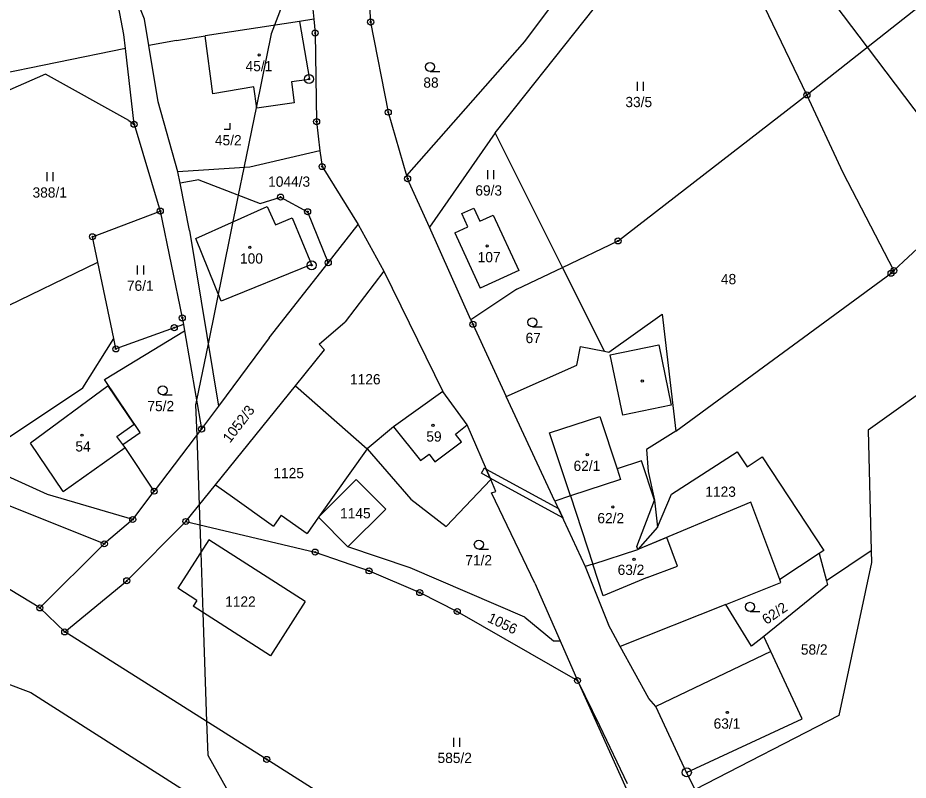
# Model space of a CAD drawing. Extents: x -547623 to -538651, y -1096714 to -1086522.
# Drawn here: x -539985 to -539837.5, y -1092582.7 to -1092456.3 of the extents above; entities that cross this region are included whole.
import ezdxf

# ---------------------------------------------------------------- set-up
doc = ezdxf.new("R2010")
doc.units = 0
for name, color, linetype in [('Vrstva 1', 7, 'Continuous'), ('Vrstva 25', 7, 'Continuous'), ('Vrstva 30', 7, 'Continuous'), ('Vrstva 33', 7, 'Continuous'), ('Vrstva 52', 7, 'Continuous'), ('Vrstva 83', 7, 'Continuous'), ('Vrstva 86', 7, 'Continuous'), ('Vrstva 90', 7, 'Continuous'), ('Vrstva 92', 7, 'Continuous')]:
    doc.layers.add(name, color=color, linetype=linetype)

msp = doc.modelspace()

# ---------------------------------------------------------------- linework, layer by layer
at = {"layer": 'Vrstva 1'}
for points in [[(-539854.24, -1092469.12), (-539880.19, -1092415.07)], [(-539927.51, -1092441.29), (-539926.51, -1092457.05)], [(-539854.24, -1092469.12), (-539819.88, -1092441.94)], [(-539889.99, -1092445.46), (-539901.05, -1092460.25)], [(-539967.38, -1092459.11), (-539969.34, -1092448.92)], [(-539963.99, -1092456.56), (-539966.38, -1092450.37)], [(-539936.59, -1092449.87), (-539935.93, -1092456.59)], [(-539905.87, -1092475.4), (-539886.21, -1092450.61)], [(-539963.24, -1092460.92), (-539963.99, -1092456.56)], [(-539938.3, -1092456.95), (-539953.92, -1092459.34)], [(-539935.93, -1092456.59), (-539938.3, -1092456.95)], [(-539938.3, -1092456.95), (-539936.64, -1092466.58)], [(-539935.93, -1092456.59), (-539935.71, -1092458.88)], [(-539926.51, -1092457.05), (-539923.6, -1092471.99)], [(-539967.12, -1092461.42), (-539967.38, -1092459.11)], [(-539958.7, -1092460.12), (-539953.92, -1092459.34)], [(-539952.63, -1092468.96), (-539953.92, -1092459.34)], [(-539935.71, -1092458.88), (-539935.47, -1092473.55)], [(-539958.7, -1092460.12), (-539963.24, -1092460.92)], [(-539961.69, -1092470.26), (-539963.24, -1092460.92)], [(-539901.05, -1092460.25), (-539920.55, -1092482.48)], [(-539967.12, -1092461.42), (-539989.83, -1092466.07)], [(-539965.7, -1092473.99), (-539967.12, -1092461.42)], [(-539980.4, -1092465.66), (-539988.59, -1092469.3)], [(-539966.56, -1092473.37), (-539980.4, -1092465.66)], [(-539936.64, -1092466.58), (-539939.65, -1092466.96)], [(-539939.65, -1092466.96), (-539939.18, -1092470.46)], [(-539945.89, -1092467.79), (-539952.63, -1092468.96)], [(-539945.39, -1092471.34), (-539945.89, -1092467.79)], [(-539885.53, -1092493.32), (-539854.24, -1092469.12)], [(-539848.22, -1092482.06), (-539854.24, -1092469.12)], [(-539958.44, -1092481.89), (-539961.69, -1092470.26)], [(-539939.18, -1092470.46), (-539945.39, -1092471.34)], [(-539923.6, -1092471.99), (-539920.55, -1092482.48)], [(-539966.56, -1092473.37), (-539965.7, -1092473.99)], [(-539965.7, -1092473.99), (-539961.36, -1092488.37)], [(-539935.47, -1092473.55), (-539934.94, -1092478.38)], [(-539905.87, -1092475.4), (-539916.79, -1092491.03)], [(-539894.73, -1092497.7), (-539905.87, -1092475.4)], [(-539934.94, -1092478.38), (-539946.54, -1092481.12)], [(-539934.94, -1092478.38), (-539934.55, -1092481)], [(-539946.54, -1092481.12), (-539958.44, -1092481.89)], [(-539958.08, -1092483.74), (-539958.44, -1092481.89)], [(-539934.55, -1092481), (-539928.56, -1092490.6)], [(-539954.99, -1092483.22), (-539958.08, -1092483.74)], [(-539954.99, -1092483.22), (-539944.84, -1092487.14)], [(-539920.55, -1092482.48), (-539920.39, -1092483.01)], [(-539916.79, -1092491.03), (-539920.39, -1092483.01)], [(-539839.84, -1092498.24), (-539848.22, -1092482.06)], [(-539956.54, -1092491.6), (-539958.08, -1092483.74)], [(-539944.84, -1092487.14), (-539941.44, -1092486.05)], [(-539941.44, -1092486.05), (-539936.95, -1092488.48)], [(-539911.4, -1092488.78), (-539909.4, -1092487.87)], [(-539909.4, -1092487.87), (-539908.41, -1092490.05)], [(-539972.59, -1092492.63), (-539961.36, -1092488.37)], [(-539961.36, -1092488.37), (-539957.71, -1092506.07)], [(-539936.95, -1092488.48), (-539933.54, -1092496.92)], [(-539910.41, -1092490.96), (-539911.4, -1092488.78)], [(-539908.41, -1092490.05), (-539906.22, -1092489.05)], [(-539906.22, -1092489.05), (-539901.94, -1092498.2)], [(-539933.54, -1092496.92), (-539928.56, -1092490.6)], [(-539928.56, -1092490.6), (-539924.33, -1092498.35)], [(-539956.54, -1092491.6), (-539951.73, -1092520.7)], [(-539909.9, -1092506.41), (-539916.79, -1092491.03)], [(-539912.59, -1092491.96), (-539910.41, -1092490.96)], [(-539912.59, -1092491.96), (-539908.39, -1092501.15)], [(-539971.72, -1092496.81), (-539972.59, -1092492.63)], [(-539894.73, -1092497.7), (-539885.53, -1092493.32)], [(-539835.1, -1092493.79), (-539839.84, -1092498.24)], [(-539988.4, -1092504.88), (-539971.72, -1092496.81)], [(-539969.08, -1092509.5), (-539971.72, -1092496.81)], [(-539943.33, -1092509.36), (-539933.54, -1092496.92)], [(-539901.94, -1092498.2), (-539908.39, -1092501.15)], [(-539902.28, -1092501.29), (-539894.73, -1092497.7)], [(-539887.8, -1092511.58), (-539894.73, -1092497.7)], [(-539839.84, -1092498.24), (-539840.31, -1092498.67)], [(-539924.33, -1092498.35), (-539930.72, -1092506.72)], [(-539924.33, -1092498.35), (-539914.58, -1092518.25)], [(-539875.95, -1092524.82), (-539840.31, -1092498.67)], [(-539902.28, -1092501.29), (-539909.9, -1092506.41)], [(-539887.07, -1092511.73), (-539878.25, -1092505.43)], [(-539878.25, -1092505.43), (-539875.95, -1092524.82)], [(-539957.71, -1092506.07), (-539957.53, -1092507.14)], [(-539935.02, -1092510.4), (-539930.72, -1092506.72)], [(-539909.9, -1092506.41), (-539909.57, -1092507.13)], [(-539970.58, -1092516.26), (-539957.34, -1092508.21)], [(-539959.05, -1092507.69), (-539968.72, -1092511.21)], [(-539957.53, -1092507.14), (-539959.05, -1092507.69)], [(-539957.53, -1092507.14), (-539957.34, -1092508.21)], [(-539957.34, -1092508.21), (-539954.52, -1092524.48)], [(-539909.57, -1092507.13), (-539904.06, -1092519.12)], [(-539974.2, -1092517.68), (-539969.08, -1092509.5)], [(-539968.72, -1092511.21), (-539969.08, -1092509.5)], [(-539943.33, -1092509.36), (-539951.73, -1092520.7)], [(-539938.96, -1092517.34), (-539934.14, -1092511.37)], [(-539934.14, -1092511.37), (-539935.02, -1092510.4)], [(-539892.37, -1092513.88), (-539891.75, -1092510.79)], [(-539891.75, -1092510.79), (-539887.8, -1092511.58)], [(-539887.8, -1092511.58), (-539887.07, -1092511.73)], [(-539904.06, -1092519.12), (-539892.37, -1092513.88)], [(-539831.12, -1092515.38), (-539844.08, -1092524.7)], [(-539964.68, -1092525.04), (-539970.58, -1092516.26)], [(-539952.21, -1092533.73), (-539938.96, -1092517.34)], [(-539938.96, -1092517.34), (-539927.08, -1092527.79)], [(-539992.38, -1092529.77), (-539974.2, -1092517.68)], [(-539914.58, -1092518.25), (-539922.72, -1092524.13)], [(-539910.51, -1092523.78), (-539914.58, -1092518.25)], [(-539895.99, -1092536.42), (-539904.06, -1092519.12)], [(-539951.73, -1092520.7), (-539954.52, -1092524.48)], [(-539970.63, -1092543.51), (-540021.91, -1092522.99)], [(-539954.52, -1092524.48), (-539962.37, -1092534.79)], [(-539922.72, -1092524.13), (-539927.08, -1092527.79)], [(-539906.6, -1092532.86), (-539910.51, -1092523.78)], [(-539844.08, -1092524.7), (-539843.61, -1092544.68)], [(-539967.54, -1092527.06), (-539964.68, -1092525.04)], [(-539875.95, -1092524.82), (-539880.81, -1092527.9)], [(-539967.18, -1092527.54), (-539967.54, -1092527.06)], [(-539962.37, -1092534.79), (-539967.18, -1092527.54)], [(-539927.08, -1092527.79), (-539935.14, -1092539.1)], [(-539927.08, -1092527.79), (-539919.83, -1092536.1)], [(-539880.81, -1092527.9), (-539880.55, -1092531.53)], [(-539876.69, -1092535.28), (-539865.82, -1092528.26)], [(-539865.82, -1092528.26), (-539864.17, -1092530.77)], [(-539864.17, -1092530.77), (-539861.65, -1092529.12)], [(-539861.65, -1092529.12), (-539851.46, -1092544.63)], [(-539980.04, -1092535.32), (-539992.38, -1092529.77)], [(-539881.62, -1092529.74), (-539885.7, -1092531.09)], [(-539879.47, -1092536.25), (-539881.62, -1092529.74)], [(-539885.7, -1092531.09), (-539885.12, -1092532.84)], [(-539880.55, -1092531.53), (-539879.47, -1092536.25)], [(-539928.89, -1092532.86), (-539935.14, -1092539.1)], [(-539924.02, -1092537.74), (-539928.89, -1092532.86)], [(-539914.01, -1092540.61), (-539906.6, -1092532.86)], [(-539905.75, -1092534.83), (-539906.6, -1092532.86)], [(-539885.12, -1092532.84), (-539893.43, -1092535.58)], [(-539965.93, -1092539.48), (-539962.37, -1092534.79)], [(-539957.12, -1092539.8), (-539952.21, -1092533.73)], [(-539952.21, -1092533.73), (-539949.81, -1092535.44)], [(-539906.5, -1092535.08), (-539905.75, -1092534.83)], [(-539899.29, -1092550.04), (-539906.5, -1092535.08)], [(-539965.93, -1092539.48), (-539980.04, -1092535.32)], [(-539949.81, -1092535.44), (-539942.61, -1092540.57)], [(-539919.83, -1092536.1), (-539914.01, -1092540.61)], [(-539893.43, -1092535.58), (-539895.99, -1092536.42)], [(-539895.99, -1092536.42), (-539890.96, -1092547.25)], [(-539879.47, -1092536.25), (-539879, -1092540.75)], [(-539879, -1092540.75), (-539876.69, -1092535.28)], [(-539981.31, -1092554.13), (-540009.05, -1092537.31)], [(-539930.27, -1092543.98), (-539924.02, -1092537.74)], [(-539863.53, -1092536.62), (-539882.25, -1092544.43)], [(-539858.74, -1092549.42), (-539863.53, -1092536.62)], [(-539965.93, -1092539.48), (-539970.63, -1092543.51)], [(-539941.31, -1092538.74), (-539942.61, -1092540.57)], [(-539941.31, -1092538.74), (-539937.05, -1092541.78)], [(-539935.14, -1092539.1), (-539937.05, -1092541.78)], [(-539930.27, -1092543.98), (-539935.14, -1092539.1)], [(-539966.91, -1092549.63), (-539957.12, -1092539.8)], [(-539957.12, -1092539.8), (-539935.71, -1092544.88)], [(-539879, -1092540.75), (-539882.25, -1092544.43)], [(-539970.63, -1092543.51), (-539981.31, -1092554.13)], [(-539953.32, -1092542.86), (-539958.45, -1092550.88)], [(-539937.35, -1092553.08), (-539953.32, -1092542.86)], [(-539935.71, -1092544.88), (-539926.78, -1092547.99)], [(-539919.98, -1092547.47), (-539930.27, -1092543.98)], [(-539889.7, -1092546.89), (-539882.25, -1092544.43)], [(-539852.21, -1092545.13), (-539858.74, -1092549.42)], [(-539851.46, -1092544.63), (-539852.21, -1092545.13)], [(-539852.21, -1092545.13), (-539851.02, -1092549.62)], [(-539843.61, -1092544.68), (-539851.02, -1092549.62)], [(-539843.61, -1092544.68), (-539843.55, -1092546.58)], [(-539889.7, -1092546.89), (-539890.96, -1092547.25)], [(-539843.55, -1092546.58), (-539848.95, -1092571.97)], [(-539926.78, -1092547.99), (-539918.39, -1092551.59)], [(-539900.95, -1092555.67), (-539919.98, -1092547.47)], [(-539890.96, -1092547.25), (-539887.13, -1092556.95)], [(-539977.19, -1092558.1), (-539966.91, -1092549.63)], [(-539858.56, -1092549.91), (-539858.74, -1092549.42)], [(-539851.02, -1092549.62), (-539850.83, -1092550.33)], [(-539955.3, -1092552.9), (-539958.45, -1092550.88)], [(-539899.29, -1092550.04), (-539895.12, -1092559.59)], [(-539867.66, -1092553.54), (-539858.56, -1092549.91)], [(-539850.83, -1092550.33), (-539861.4, -1092558.84)], [(-539918.39, -1092551.59), (-539912.17, -1092554.72)], [(-539981.31, -1092554.13), (-539977.19, -1092558.1)], [(-539955.3, -1092552.9), (-539955.9, -1092553.85)], [(-539943.08, -1092562.05), (-539955.9, -1092553.85)], [(-539937.35, -1092553.08), (-539943.08, -1092562.05)], [(-539867.66, -1092553.54), (-539885.17, -1092560.52)], [(-539863.44, -1092560.48), (-539867.66, -1092553.54)], [(-539912.17, -1092554.72), (-539892.25, -1092566.16)], [(-539900.95, -1092555.67), (-539896.24, -1092559.58)], [(-539885.17, -1092560.52), (-539887.13, -1092556.95)], [(-539943.72, -1092579.23), (-539977.19, -1092558.1)], [(-539896.24, -1092559.58), (-539895.12, -1092559.59)], [(-539895.12, -1092559.59), (-539892.25, -1092566.16)], [(-539861.4, -1092558.84), (-539863.44, -1092560.48)], [(-539860.22, -1092561.37), (-539861.4, -1092558.84)], [(-539880.44, -1092569.13), (-539885.17, -1092560.52)], [(-539855.04, -1092572.53), (-539860.22, -1092561.37)], [(-539987.04, -1092566.54), (-539982.78, -1092568.14)], [(-539892.25, -1092566.16), (-539876.34, -1092601.43)], [(-539892.25, -1092566.16), (-539888.59, -1092573.61)], [(-539982.78, -1092568.14), (-539937.51, -1092597.02)], [(-539879.27, -1092570.44), (-539880.44, -1092569.13)], [(-539874.17, -1092581.42), (-539879.27, -1092570.44)], [(-539848.95, -1092571.97), (-539872.78, -1092584.22)], [(-539874.17, -1092581.42), (-539855.04, -1092572.53)], [(-539888.59, -1092573.61), (-539884.01, -1092583.21)], [(-539930.72, -1092587.47), (-539943.72, -1092579.23)], [(-539872.78, -1092584.22), (-539874.17, -1092581.42)]]:
    msp.add_lwpolyline(points, dxfattribs=at)
at = {"layer": 'Vrstva 25'}
for p, q in [((-539916.68, -1092465.23), (-539915.08, -1092465.23)), ((-539882.3, -1092468.45), (-539882.3, -1092466.95)), ((-539881.3, -1092468.45), (-539881.3, -1092466.95)), ((-539980.11, -1092483.44), (-539980.11, -1092481.94)), ((-539979.11, -1092483.44), (-539979.11, -1092481.94)), ((-539907.11, -1092483.1), (-539907.11, -1092481.6)), ((-539906.11, -1092483.1), (-539906.11, -1092481.6)), ((-539965.11, -1092498.88), (-539965.11, -1092497.38)), ((-539964.11, -1092498.88), (-539964.11, -1092497.38)), ((-539899.71, -1092507.55), (-539898.11, -1092507.55)), ((-539960.98, -1092518.83), (-539959.38, -1092518.83)), ((-539908.59, -1092544.38), (-539906.99, -1092544.38)), ((-539863.66, -1092554.7), (-539862.06, -1092554.7)), ((-539912.75, -1092577.13), (-539912.75, -1092575.63)), ((-539911.75, -1092577.13), (-539911.75, -1092575.63))]:
    msp.add_line(p, q, dxfattribs=at)
msp.add_lwpolyline([(-539950.8, -1092474.78), (-539949.8, -1092474.78), (-539949.8, -1092473.78)], dxfattribs=at)
for centre, radius in [((-539944.99, -1092462.5), 0.175), ((-539916.68, -1092464.48), 0.75), ((-539946.52, -1092494.37), 0.175), ((-539907.22, -1092494.15), 0.175), ((-539899.71, -1092506.8), 0.75), ((-539960.98, -1092518.08), 0.75), ((-539881.51, -1092516.53), 0.175), ((-539916.19, -1092523.87), 0.175), ((-539974.32, -1092525.51), 0.175), ((-539890.62, -1092528.73), 0.175), ((-539886.4, -1092537.4), 0.175), ((-539908.59, -1092543.63), 0.75), ((-539882.88, -1092546.07), 0.175), ((-539863.66, -1092553.95), 0.75), ((-539867.42, -1092571.44), 0.175)]:
    msp.add_circle(centre, radius, dxfattribs=at)
at = {"layer": 'Vrstva 30'}
for points in [[(-539908.15, -1092531.82), (-539907.67, -1092530.94)], [(-539906.71, -1092532.61), (-539908.15, -1092531.82)], [(-539907.67, -1092530.94), (-539907.35, -1092531.11)], [(-539907.35, -1092531.11), (-539906.71, -1092532.61)], [(-539907.35, -1092531.11), (-539895.41, -1092537.67)], [(-539906.71, -1092532.61), (-539907.35, -1092531.11)], [(-539894.7, -1092539.19), (-539906.71, -1092532.61)], [(-539895.41, -1092537.67), (-539894.7, -1092539.19)]]:
    msp.add_lwpolyline(points, dxfattribs=at)
at = {"layer": 'Vrstva 33'}
for points in [[(-539955.48, -1092492.93), (-539943.63, -1092487.61)], [(-539943.63, -1092487.61), (-539942.26, -1092490.67)], [(-539942.26, -1092490.67), (-539939.51, -1092489.47)], [(-539939.51, -1092489.47), (-539936.3, -1092497.25)], [(-539951.27, -1092503.32), (-539955.48, -1092492.93)], [(-539936.3, -1092497.25), (-539951.27, -1092503.32)], [(-539886.81, -1092512.19), (-539878.78, -1092510.53)], [(-539878.78, -1092510.53), (-539876.72, -1092520.52)], [(-539884.75, -1092522.18), (-539886.81, -1092512.19)], [(-539969.99, -1092517.31), (-539982.88, -1092526.84)], [(-539965.69, -1092523.7), (-539969.99, -1092517.31)], [(-539876.72, -1092520.52), (-539884.75, -1092522.18)], [(-539896.87, -1092525.14), (-539888.56, -1092522.4)], [(-539888.56, -1092522.4), (-539885.7, -1092531.09)], [(-539968.55, -1092525.72), (-539965.69, -1092523.7)], [(-539922.72, -1092524.13), (-539918.26, -1092529.72)], [(-539912.43, -1092525.34), (-539910.51, -1092523.78)], [(-539967.54, -1092527.06), (-539968.55, -1092525.72)], [(-539911.47, -1092526.62), (-539912.43, -1092525.34)], [(-539893.43, -1092535.58), (-539896.87, -1092525.14)], [(-539977.44, -1092534.86), (-539982.88, -1092526.84)], [(-539977.44, -1092534.86), (-539967.18, -1092527.54)], [(-539915.86, -1092529.92), (-539911.47, -1092526.62)], [(-539918.26, -1092529.72), (-539916.82, -1092528.64)], [(-539916.82, -1092528.64), (-539915.86, -1092529.92)], [(-539893.43, -1092535.58), (-539889.7, -1092546.89)], [(-539882.4, -1092543.95), (-539879.47, -1092536.25)], [(-539877.46, -1092542.46), (-539882.25, -1092544.43)], [(-539875.7, -1092547.19), (-539877.46, -1092542.46)], [(-539882.25, -1092544.43), (-539882.4, -1092543.95)], [(-539888, -1092552.1), (-539889.7, -1092546.89)], [(-539880.71, -1092549.09), (-539875.7, -1092547.19)], [(-539880.71, -1092549.09), (-539888, -1092552.1)], [(-539860.22, -1092561.37), (-539879.27, -1092570.44)]]:
    msp.add_lwpolyline(points, dxfattribs=at)
at = {"layer": 'Vrstva 52'}
for points in [[(-539911.5, -1092362), (-539906.38, -1092370.45), (-539898.01, -1092384.26), (-539889.98, -1092397.52), (-539886.91, -1092402.59), (-539880, -1092414), (-539879.9, -1092414.13), (-539844.26, -1092461.23), (-539824.16, -1092487.78), (-539808.2, -1092508.88), (-539754, -1092580.5), (-539709.23, -1092619.45), (-539642.5, -1092677.5), (-539608.53, -1092701.71), (-539605.85, -1092703.62), (-539548.9, -1092744.22), (-539548.5, -1092744.5), (-539431, -1092815)], [(-539937.11, -1092443.55), (-539942.46, -1092457.59), (-539943, -1092459), (-539945.44, -1092471), (-539947.51, -1092481.18), (-539948.44, -1092485.75), (-539953.44, -1092510.36), (-539955.34, -1092519.73), (-539955.5, -1092520.5), (-539955.33, -1092525.54), (-539954.93, -1092537.09), (-539954.82, -1092540.35), (-539954.66, -1092544.95), (-539954.32, -1092554.86), (-539953.69, -1092572.93), (-539953.5, -1092578.5), (-539946.26, -1092591.44), (-539933.27, -1092614.65), (-539923, -1092633), (-539897.5, -1092666.5)]]:
    msp.add_lwpolyline(points, dxfattribs=at)
at = {"layer": 'Vrstva 83'}
for centre, radius in [((-539926.51, -1092457.05), 0.5), ((-539926.51, -1092457.05), 0.1), ((-539935.71, -1092458.88), 0.5), ((-539935.71, -1092458.88), 0.1), ((-539936.71, -1092466.5), 0.75), ((-539936.71, -1092466.5), 0.1), ((-539854.24, -1092469.12), 0.5), ((-539854.24, -1092469.12), 0.1), ((-539923.6, -1092471.99), 0.5), ((-539935.47, -1092473.55), 0.5), ((-539923.6, -1092471.99), 0.1), ((-539965.7, -1092473.99), 0.5), ((-539965.7, -1092473.99), 0.1), ((-539935.47, -1092473.55), 0.1), ((-539934.55, -1092481), 0.5), ((-539934.55, -1092481), 0.1), ((-539920.39, -1092483.01), 0.5), ((-539920.39, -1092483.01), 0.1), ((-539941.44, -1092486.05), 0.5), ((-539941.44, -1092486.05), 0.1), ((-539961.36, -1092488.37), 0.5), ((-539961.36, -1092488.37), 0.1), ((-539936.95, -1092488.48), 0.5), ((-539936.95, -1092488.48), 0.1), ((-539972.59, -1092492.63), 0.5), ((-539972.59, -1092492.63), 0.1), ((-539885.53, -1092493.32), 0.5), ((-539885.53, -1092493.32), 0.1), ((-539936.27, -1092497.36), 0.75), ((-539933.54, -1092496.92), 0.5), ((-539936.27, -1092497.36), 0.1), ((-539933.54, -1092496.92), 0.1), ((-539840.31, -1092498.67), 0.5), ((-539839.84, -1092498.24), 0.5), ((-539839.84, -1092498.24), 0.1), ((-539840.31, -1092498.67), 0.1), ((-539957.71, -1092506.07), 0.5), ((-539957.71, -1092506.07), 0.1), ((-539909.57, -1092507.13), 0.5), ((-539909.57, -1092507.13), 0.1), ((-539959.05, -1092507.69), 0.5), ((-539959.05, -1092507.69), 0.1), ((-539968.72, -1092511.21), 0.5), ((-539968.72, -1092511.21), 0.1), ((-539954.52, -1092524.48), 0.5), ((-539954.52, -1092524.48), 0.1), ((-539962.37, -1092534.79), 0.5), ((-539962.37, -1092534.79), 0.1), ((-539965.93, -1092539.48), 0.5), ((-539965.93, -1092539.48), 0.1), ((-539957.12, -1092539.8), 0.5), ((-539957.12, -1092539.8), 0.1), ((-539970.63, -1092543.51), 0.5), ((-539970.63, -1092543.51), 0.1), ((-539935.71, -1092544.88), 0.5), ((-539935.71, -1092544.88), 0.1), ((-539926.78, -1092547.99), 0.5), ((-539926.78, -1092547.99), 0.1), ((-539966.91, -1092549.63), 0.5), ((-539966.91, -1092549.63), 0.1), ((-539918.39, -1092551.59), 0.5), ((-539918.39, -1092551.59), 0.1), ((-539981.31, -1092554.13), 0.5), ((-539981.31, -1092554.13), 0.1), ((-539912.17, -1092554.72), 0.5), ((-539912.17, -1092554.72), 0.1), ((-539977.19, -1092558.1), 0.5), ((-539977.19, -1092558.1), 0.1), ((-539892.25, -1092566.16), 0.5), ((-539892.25, -1092566.16), 0.1), ((-539943.72, -1092579.23), 0.5), ((-539943.72, -1092579.23), 0.1), ((-539874.14, -1092581.39), 0.75), ((-539874.14, -1092581.39), 0.1)]:
    msp.add_circle(centre, radius, dxfattribs=at)
at = {"layer": 'Vrstva 90'}
for points in [[(-539938.3, -1092456.95), (-539953.92, -1092459.34)], [(-539938.3, -1092456.95), (-539936.64, -1092466.58)], [(-539952.63, -1092468.96), (-539953.92, -1092459.34)], [(-539936.64, -1092466.58), (-539939.65, -1092466.96)], [(-539939.65, -1092466.96), (-539939.18, -1092470.46)], [(-539945.89, -1092467.79), (-539952.63, -1092468.96)], [(-539945.39, -1092471.34), (-539945.89, -1092467.79)], [(-539939.18, -1092470.46), (-539945.39, -1092471.34)], [(-539955.48, -1092492.93), (-539943.63, -1092487.61)], [(-539943.63, -1092487.61), (-539942.26, -1092490.67)], [(-539911.4, -1092488.78), (-539909.4, -1092487.87)], [(-539909.4, -1092487.87), (-539908.41, -1092490.05)], [(-539910.41, -1092490.96), (-539911.4, -1092488.78)], [(-539908.41, -1092490.05), (-539906.22, -1092489.05)], [(-539906.22, -1092489.05), (-539901.94, -1092498.2)], [(-539942.26, -1092490.67), (-539939.51, -1092489.47)], [(-539939.51, -1092489.47), (-539936.3, -1092497.25)], [(-539912.59, -1092491.96), (-539910.41, -1092490.96)], [(-539912.59, -1092491.96), (-539908.39, -1092501.15)], [(-539951.27, -1092503.32), (-539955.48, -1092492.93)], [(-539936.3, -1092497.25), (-539951.27, -1092503.32)], [(-539901.94, -1092498.2), (-539908.39, -1092501.15)], [(-539969.99, -1092517.31), (-539982.88, -1092526.84)], [(-539965.69, -1092523.7), (-539969.99, -1092517.31)], [(-539914.58, -1092518.25), (-539922.72, -1092524.13)], [(-539910.51, -1092523.78), (-539914.58, -1092518.25)], [(-539896.87, -1092525.14), (-539888.56, -1092522.4)], [(-539888.56, -1092522.4), (-539885.7, -1092531.09)], [(-539968.55, -1092525.72), (-539965.69, -1092523.7)], [(-539922.72, -1092524.13), (-539918.26, -1092529.72)], [(-539912.43, -1092525.34), (-539910.51, -1092523.78)], [(-539967.54, -1092527.06), (-539968.55, -1092525.72)], [(-539911.47, -1092526.62), (-539912.43, -1092525.34)], [(-539893.43, -1092535.58), (-539896.87, -1092525.14)], [(-539977.44, -1092534.86), (-539982.88, -1092526.84)], [(-539977.44, -1092534.86), (-539967.18, -1092527.54)], [(-539967.18, -1092527.54), (-539967.54, -1092527.06)], [(-539915.86, -1092529.92), (-539911.47, -1092526.62)], [(-539918.26, -1092529.72), (-539916.82, -1092528.64)], [(-539916.82, -1092528.64), (-539915.86, -1092529.92)], [(-539881.62, -1092529.74), (-539885.7, -1092531.09)], [(-539879.47, -1092536.25), (-539881.62, -1092529.74)], [(-539885.7, -1092531.09), (-539885.12, -1092532.84)], [(-539885.7, -1092531.09), (-539885.12, -1092532.84)], [(-539885.12, -1092532.84), (-539893.43, -1092535.58)], [(-539885.12, -1092532.84), (-539893.43, -1092535.58)], [(-539893.43, -1092535.58), (-539889.7, -1092546.89)], [(-539882.4, -1092543.95), (-539879.47, -1092536.25)], [(-539877.46, -1092542.46), (-539882.25, -1092544.43)], [(-539875.7, -1092547.19), (-539877.46, -1092542.46)], [(-539882.25, -1092544.43), (-539882.4, -1092543.95)], [(-539889.7, -1092546.89), (-539882.25, -1092544.43)], [(-539889.7, -1092546.89), (-539882.25, -1092544.43)], [(-539888, -1092552.1), (-539889.7, -1092546.89)], [(-539880.71, -1092549.09), (-539875.7, -1092547.19)], [(-539880.71, -1092549.09), (-539888, -1092552.1)], [(-539860.22, -1092561.37), (-539879.27, -1092570.44)], [(-539855.04, -1092572.53), (-539860.22, -1092561.37)], [(-539874.17, -1092581.42), (-539879.27, -1092570.44)], [(-539874.17, -1092581.42), (-539855.04, -1092572.53)]]:
    msp.add_lwpolyline(points, dxfattribs=at)

# ---------------------------------------------------------------- texts
at = {"layer": 'Vrstva 86'}
for s, p in [('88', (-539917.78, -1092467.93)), ('33/5', (-539884.31, -1092471.15)), ('1044/3', (-539943.49, -1092484.34)), ('388/1', (-539982.52, -1092486.14)), ('69/3', (-539909.17, -1092485.8)), ('48', (-539868.49, -1092500.49)), ('76/1', (-539966.89, -1092501.58)), ('67', (-539900.85, -1092510.25)), ('1126', (-539929.93, -1092517.09)), ('75/2', (-539963.49, -1092521.53)), ('1125', (-539942.62, -1092532.63)), ('1123', (-539871.07, -1092535.72)), ('1145', (-539931.57, -1092539.29)), ('71/2', (-539910.83, -1092547.08)), ('1122', (-539950.61, -1092553.93)), ('58/2', (-539855.25, -1092561.87)), ('585/2', (-539915.43, -1092579.83))]:
    msp.add_text(s, height=1.7, dxfattribs=at).set_placement(p)
for s, rotation, p in [('1052/3', 52.7153, (-539949.82, -1092526.91)), ('62/2', 34.3951, (-539860.94, -1092556.96)), ('1056', 334.3878, (-539907.3, -1092556.37))]:
    msp.add_text(s, height=1.7, rotation=rotation, dxfattribs=at).set_placement(p)
at = {"layer": 'Vrstva 92'}
for s, p in [('45/1', (-539947.23, -1092465.2)), ('45/2', (-539952.31, -1092477.48)), ('107', (-539908.78, -1092496.85)), ('100', (-539948.15, -1092497.07)), ('59', (-539917.29, -1092526.57)), ('54', (-539975.42, -1092528.21)), ('62/1', (-539892.9, -1092531.43)), ('62/2', (-539888.95, -1092540.1)), ('63/2', (-539885.6, -1092548.66)), ('63/1', (-539869.7, -1092574.14))]:
    msp.add_text(s, height=1.7, dxfattribs=at).set_placement(p)

doc.saveas('drawing.dxf')
